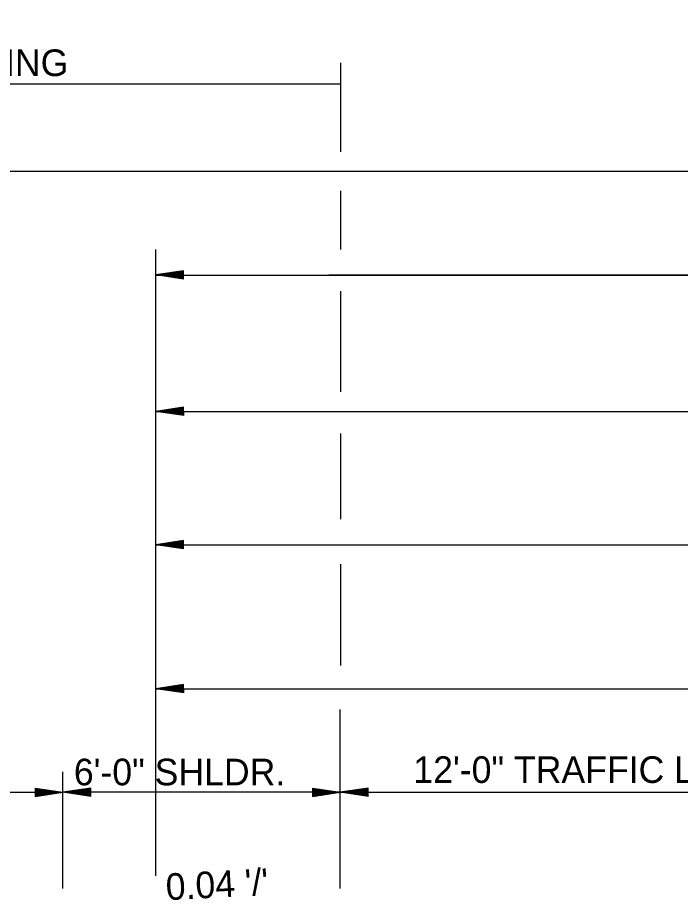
# Model space of a CAD drawing. Extents: x 1364961 to 1365294, y 367927 to 368034.
# Drawn here: x 1365186.52 to 1365200.85, y 367972.72 to 367991.83 of the extents above; entities that cross this region are included whole.
import ezdxf

# ---------------------------------------------------------------- set-up
doc = ezdxf.new("R2010")
doc.units = 0
doc.layers.add('Default', color=7, linetype='Continuous')

msp = doc.modelspace()

# ---------------------------------------------------------------- linework, layer by layer
at = {"layer": 'Default'}
for p, q in [((1365193.509, 367988.923), (1365193.509, 367990.85)), ((1365175.498, 367988.505), (1365247.538, 367988.505)), ((1365193.509, 367986.807), (1365193.509, 367988.081)), ((1365189.509, 367973.249), (1365189.509, 367986.807)), ((1365190.109, 367986.347), (1365189.509, 367986.257)), ((1365190.109, 367986.332), (1365189.609, 367986.257)), ((1365190.109, 367986.317), (1365189.712, 367986.257)), ((1365190.109, 367986.167), (1365190.109, 367986.347)), ((1365190.109, 367986.167), (1365189.509, 367986.257)), ((1365189.509, 367986.255), (1365235.476, 367986.255)), ((1365190.109, 367986.182), (1365189.609, 367986.257)), ((1365190.109, 367986.197), (1365189.712, 367986.257)), ((1365190.109, 367986.302), (1365189.812, 367986.257)), ((1365190.109, 367986.212), (1365189.812, 367986.257)), ((1365190.109, 367986.286), (1365189.914, 367986.257)), ((1365190.109, 367986.228), (1365189.914, 367986.257)), ((1365190.109, 367986.271), (1365190.014, 367986.257)), ((1365190.109, 367986.243), (1365190.014, 367986.257)), ((1365193.249, 367986.257), (1365217.737, 367986.257)), ((1365193.509, 367983.727), (1365193.509, 367985.903)), ((1365190.109, 367983.396), (1365189.509, 367983.303)), ((1365190.11, 367983.216), (1365189.509, 367983.303)), ((1365189.509, 367983.303), (1365235.476, 367983.3)), ((1365190.109, 367983.381), (1365189.609, 367983.303)), ((1365190.109, 367983.231), (1365189.609, 367983.303)), ((1365190.109, 367983.366), (1365189.712, 367983.304)), ((1365190.109, 367983.246), (1365189.712, 367983.304)), ((1365190.109, 367983.351), (1365189.812, 367983.304)), ((1365190.109, 367983.261), (1365189.812, 367983.304)), ((1365190.109, 367983.335), (1365189.914, 367983.305)), ((1365190.109, 367983.277), (1365189.914, 367983.305)), ((1365190.109, 367983.32), (1365190.014, 367983.305)), ((1365190.109, 367983.292), (1365190.014, 367983.305)), ((1365190.11, 367983.216), (1365190.109, 367983.396)), ((1365193.509, 367980.97), (1365193.509, 367982.828)), ((1365190.109, 367980.508), (1365189.509, 367980.418)), ((1365189.509, 367980.418), (1365235.476, 367980.418)), ((1365190.109, 367980.328), (1365189.509, 367980.418)), ((1365190.109, 367980.493), (1365189.609, 367980.418)), ((1365190.109, 367980.343), (1365189.609, 367980.418)), ((1365190.109, 367980.478), (1365189.712, 367980.418)), ((1365190.109, 367980.358), (1365189.712, 367980.418)), ((1365190.109, 367980.463), (1365189.812, 367980.418)), ((1365190.109, 367980.373), (1365189.812, 367980.418)), ((1365190.109, 367980.447), (1365189.914, 367980.418)), ((1365190.109, 367980.389), (1365189.914, 367980.418)), ((1365190.109, 367980.432), (1365190.014, 367980.418)), ((1365190.109, 367980.404), (1365190.014, 367980.418)), ((1365190.109, 367980.328), (1365190.109, 367980.508)), ((1365193.249, 367980.419), (1365217.737, 367980.419)), ((1365193.509, 367977.806), (1365193.509, 367979.994)), ((1365190.109, 367977.394), (1365189.509, 367977.301)), ((1365190.109, 367977.379), (1365189.609, 367977.302)), ((1365190.109, 367977.364), (1365189.712, 367977.302)), ((1365190.109, 367977.349), (1365189.812, 367977.303)), ((1365190.109, 367977.333), (1365189.914, 367977.303)), ((1365190.11, 367977.214), (1365190.109, 367977.394)), ((1365189.509, 367977.301), (1365192.957, 367977.301)), ((1365190.11, 367977.214), (1365189.509, 367977.301)), ((1365190.109, 367977.229), (1365189.609, 367977.302)), ((1365190.109, 367977.244), (1365189.712, 367977.302)), ((1365190.109, 367977.259), (1365189.812, 367977.303)), ((1365190.109, 367977.275), (1365189.914, 367977.303)), ((1365190.109, 367977.318), (1365190.014, 367977.304)), ((1365190.109, 367977.29), (1365190.014, 367977.304)), ((1365192.957, 367977.301), (1365218.049, 367977.301)), ((1365193.498, 367972.974), (1365193.498, 367976.85)), ((1365187.498, 367972.974), (1365187.498, 367975.501)), ((1365175.498, 367975.059), (1365187.498, 367975.059)), ((1365186.898, 367975.149), (1365187.498, 367975.059)), ((1365186.898, 367975.149), (1365186.898, 367974.969)), ((1365186.898, 367975.134), (1365187.398, 367975.059)), ((1365186.898, 367975.119), (1365187.295, 367975.059)), ((1365186.898, 367975.104), (1365187.195, 367975.059)), ((1365186.898, 367975.088), (1365187.093, 367975.059)), ((1365186.898, 367975.073), (1365186.993, 367975.059)), ((1365186.898, 367974.969), (1365187.498, 367975.059)), ((1365186.898, 367975.03), (1365187.093, 367975.059)), ((1365186.898, 367974.999), (1365187.295, 367975.059)), ((1365186.898, 367974.984), (1365187.398, 367975.059)), ((1365186.898, 367975.014), (1365187.195, 367975.059)), ((1365186.898, 367975.045), (1365186.993, 367975.059)), ((1365188.098, 367975.149), (1365187.498, 367975.059)), ((1365188.098, 367975.149), (1365187.498, 367975.059)), ((1365188.098, 367974.969), (1365187.498, 367975.059)), ((1365188.098, 367974.969), (1365187.498, 367975.059)), ((1365193.498, 367975.059), (1365187.498, 367975.059)), ((1365188.098, 367975.134), (1365187.598, 367975.059)), ((1365188.098, 367975.134), (1365187.598, 367975.059)), ((1365188.098, 367974.984), (1365187.598, 367975.059)), ((1365188.098, 367974.984), (1365187.598, 367975.059)), ((1365188.098, 367975.119), (1365187.701, 367975.059)), ((1365188.098, 367975.119), (1365187.701, 367975.059)), ((1365188.098, 367974.999), (1365187.701, 367975.059)), ((1365188.098, 367974.999), (1365187.701, 367975.059)), ((1365188.098, 367975.104), (1365187.801, 367975.059)), ((1365188.098, 367975.104), (1365187.801, 367975.059)), ((1365188.098, 367975.014), (1365187.801, 367975.059)), ((1365188.098, 367975.014), (1365187.801, 367975.059)), ((1365188.098, 367975.088), (1365187.903, 367975.059)), ((1365188.098, 367975.088), (1365187.903, 367975.059)), ((1365188.098, 367975.03), (1365187.903, 367975.059)), ((1365188.098, 367975.03), (1365187.903, 367975.059)), ((1365188.098, 367975.073), (1365188.003, 367975.059)), ((1365188.098, 367975.073), (1365188.003, 367975.059)), ((1365188.098, 367975.045), (1365188.003, 367975.059)), ((1365188.098, 367975.045), (1365188.003, 367975.059)), ((1365188.098, 367974.969), (1365188.098, 367975.149)), ((1365188.098, 367974.969), (1365188.098, 367975.149)), ((1365192.898, 367975.149), (1365193.498, 367975.059)), ((1365192.898, 367975.149), (1365192.898, 367974.969)), ((1365192.898, 367975.134), (1365193.398, 367975.059)), ((1365192.898, 367975.119), (1365193.295, 367975.059)), ((1365192.898, 367975.104), (1365193.195, 367975.059)), ((1365192.898, 367975.088), (1365193.093, 367975.059)), ((1365192.898, 367975.073), (1365192.993, 367975.059)), ((1365192.898, 367974.969), (1365193.498, 367975.059)), ((1365192.898, 367975.03), (1365193.093, 367975.059)), ((1365192.898, 367974.999), (1365193.295, 367975.059)), ((1365192.898, 367974.984), (1365193.398, 367975.059)), ((1365192.898, 367975.014), (1365193.195, 367975.059)), ((1365192.898, 367975.045), (1365192.993, 367975.059)), ((1365194.098, 367975.149), (1365193.498, 367975.059)), ((1365193.498, 367975.059), (1365205.498, 367975.059)), ((1365194.098, 367974.969), (1365193.498, 367975.059)), ((1365194.098, 367975.134), (1365193.598, 367975.059)), ((1365194.098, 367974.984), (1365193.598, 367975.059)), ((1365194.098, 367975.119), (1365193.701, 367975.059)), ((1365194.098, 367974.999), (1365193.701, 367975.059)), ((1365194.098, 367975.104), (1365193.801, 367975.059)), ((1365194.098, 367975.014), (1365193.801, 367975.059)), ((1365194.098, 367975.088), (1365193.903, 367975.059)), ((1365194.098, 367975.03), (1365193.903, 367975.059)), ((1365194.098, 367975.073), (1365194.003, 367975.059)), ((1365194.098, 367975.045), (1365194.003, 367975.059)), ((1365194.098, 367974.969), (1365194.098, 367975.149))]:
    msp.add_line(p, q, dxfattribs=at)
msp.add_lwpolyline([(1365193.509, 367990.387), (1365173.609, 367990.387), (1365172.752, 367991.826), (1365172.324, 367988.47), (1365171.895, 367990.387), (1365163.509, 367990.387)], dxfattribs=at)

# ---------------------------------------------------------------- texts
for s, p in [('30\'-0" SPECIAL CLEARING', (1365178.033, 367990.562)), ('12\'-0" TRAFFIC LANE', (1365195.079, 367975.262)), ('6\'-0" SHLDR.', (1365187.734, 367975.211))]:
    msp.add_text(s, height=0.576, dxfattribs=at).set_placement(p)
msp.add_text("0.04 '/'", height=0.576, rotation=3, dxfattribs=at).set_placement((1365189.737, 367972.723))

doc.saveas('drawing.dxf')
